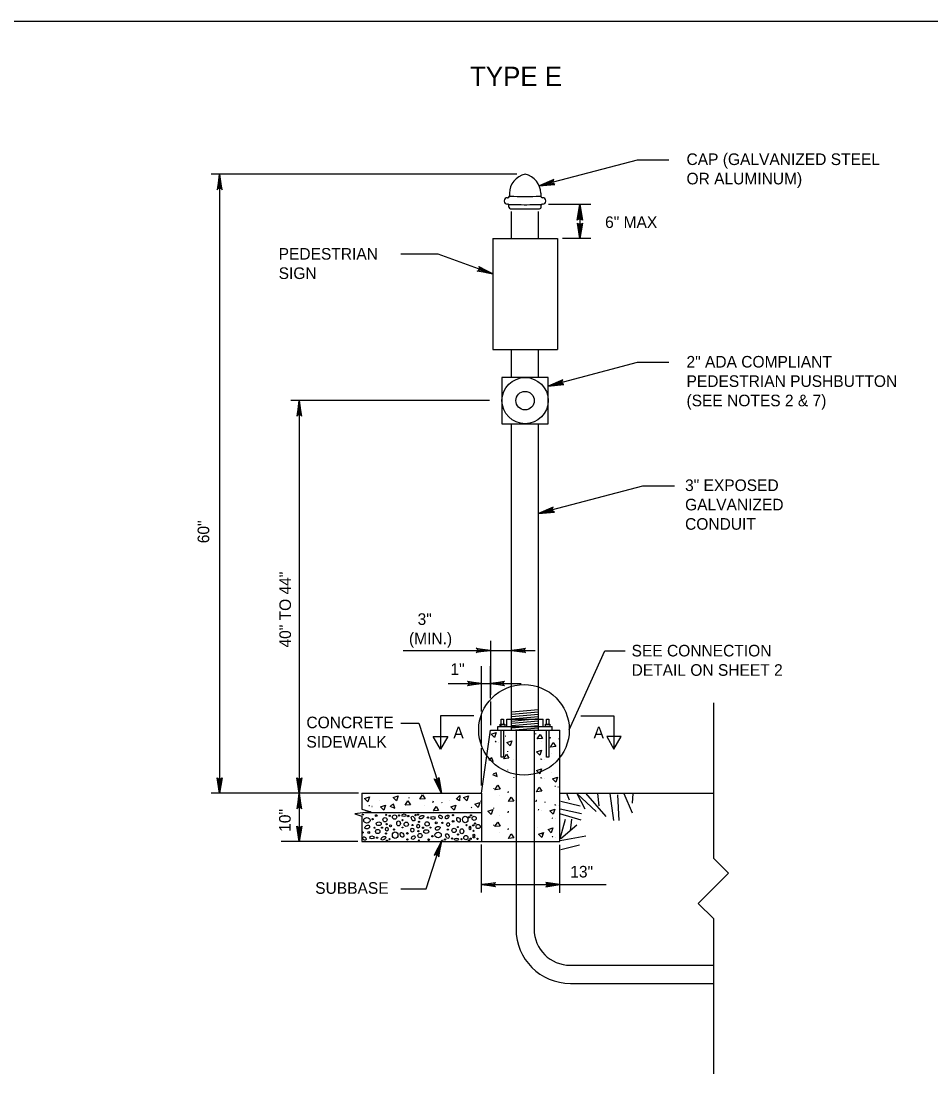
# Model space of a CAD drawing. Extents: x 36 to 940, y -1166 to 1210.
# Drawn here: x 329.9 to 564.8, y -264.7 to 7.2 of the extents above; entities that cross this region are included whole.
import ezdxf

# ---------------------------------------------------------------- set-up
doc = ezdxf.new("R2010")
doc.units = 0
for name, color, linetype in [('1', 7, 'Continuous'), ('2', 7, 'Continuous'), ('Default', 7, 'Continuous'), ('DIM TXT', 7, 'Continuous')]:
    doc.layers.add(name, color=color, linetype=linetype)

msp = doc.modelspace()

# ---------------------------------------------------------------- linework, layer by layer
at = {"layer": '1'}
for p, q in [((75.86, 7.17), (861.86, 7.17)), ((488.95, -28.72), (463.7, -35.39)), ((497.16, -28.72), (488.95, -28.72)), ((476.98, -40.17), (466.11, -40.17)), ((474.19, -40.17), (474.19, -49)), ((476.98, -49), (469.71, -49)), ((427.98, -52.97), (437.5, -52.97)), ((437.5, -52.97), (451.69, -58.09)), ((488.95, -81.02), (466.01, -87.09)), ((497.16, -81.02), (488.95, -81.02)), ((490.37, -112.9), (463.55, -119.99)), ((498.58, -112.9), (490.37, -112.9)), ((451.08, -152.85), (451.08, -166.8)), ((428.61, -155.34), (462.68, -155.34)), ((471.46, -175.86), (480.61, -155.5)), ((480.61, -155.5), (485.84, -155.5)), ((448.81, -171.16), (448.81, -159.38)), ((451.08, -167.64), (451.08, -159.38)), ((440.17, -163.88), (458.99, -163.88)), ((451.08, -168.57), (451.08, -174.69)), ((456.53, -171.24), (463.55, -170.62)), ((456.53, -171.82), (463.55, -171.21)), ((448.81, -179.38), (448.81, -172.19)), ((455.37, -175), (455.37, -173.13)), ((455.37, -173.13), (464.72, -173.13)), ((455.37, -175), (455.37, -173.13)), ((456.53, -172.41), (463.55, -171.8)), ((456.53, -173), (463.55, -172.38)), ((456.53, -173.58), (463.55, -172.97)), ((456.53, -174.17), (463.55, -173.56)), ((464.72, -175), (464.72, -173.13)), ((464.72, -175), (464.72, -173.13)), ((427.98, -174.15), (432.64, -174.15)), ((432.64, -174.15), (438.44, -192.17)), ((453.03, -175.93), (453.03, -175)), ((453.03, -175), (467.06, -175)), ((453.03, -175.93), (453.03, -175)), ((453.03, -175.93), (467.06, -175.93)), ((456.53, -174.76), (463.55, -174.14)), ((456.53, -175.34), (463.55, -174.73)), ((456.53, -175.93), (463.55, -175.32)), ((467.06, -175.93), (467.06, -175)), ((467.06, -175.93), (467.06, -175)), ((448.81, -190.24), (448.81, -180.59)), ((401.72, -192.24), (401.72, -204.72)), ((417.87, -192.24), (448.81, -192.24)), ((469.01, -192.24), (508.66, -192.24)), ((470.73, -192.24), (471.41, -193.92)), ((473.37, -192.31), (475.51, -196.25)), ((473.37, -192.31), (478.37, -196.96)), ((475.61, -192.24), (480.87, -198.21)), ((478.73, -192.31), (479.08, -195.52)), ((481.95, -192.31), (482.84, -199.28)), ((483.91, -192.67), (484.27, -199.28)), ((485.53, -192.31), (487.67, -197.32)), ((487.84, -192.31), (487.67, -194.82)), ((469.25, -194.27), (474.26, -195.52)), ((418.57, -197.23), (448.81, -197.23)), ((468.9, -197.49), (474.44, -199.1)), ((469.08, -196.25), (474.62, -197.49)), ((469.08, -203.92), (470.5, -198.92)), ((469.25, -203.92), (473.37, -200.36)), ((471.75, -201.96), (472.12, -198.92)), ((469.08, -204.46), (475.69, -203.21)), ((416.86, -204.72), (397.04, -204.72)), ((417.87, -204.72), (448.81, -204.72)), ((434.49, -216.9), (438.44, -204.63)), ((448.81, -217.88), (448.81, -205.48)), ((469.01, -217.99), (469.01, -205.56)), ((469.25, -206.79), (474.08, -205.54)), ((427.98, -216.9), (434.49, -216.9)), ((448.81, -215.84), (481.02, -215.84))]:
    msp.add_line(p, q, dxfattribs=at)
for points in [[(381.64, -36.18), (381.37, -36.03), (381.16, -32.35), (381.64, -36.18), (381.81, -36.37), (381.16, -32.35), (380.98, -36.03), (380.71, -36.16), (381.16, -32.35), (380.52, -36.37), (380.71, -36.16)], [(467.28, -33.98), (467.21, -34.28), (463.7, -35.39), (467.28, -33.98), (467.43, -33.77), (463.7, -35.39), (467.3, -34.66), (467.5, -34.89), (463.7, -35.39), (467.75, -35.02), (467.5, -34.89)], [(473.7, -44.05), (473.98, -43.91), (474.19, -40.17), (473.7, -44.05), (473.53, -44.25), (474.19, -40.17), (474.37, -43.9), (474.65, -44.04), (474.19, -40.17), (474.84, -44.25), (474.65, -44.04)], [(474.67, -45.18), (474.39, -45.32), (474.19, -49), (474.67, -45.18), (474.83, -44.98), (474.19, -49), (474, -45.32), (473.73, -45.19), (474.19, -49), (473.55, -44.98), (473.73, -45.19)], [(448.21, -56.41), (448.26, -56.72), (451.69, -58.09), (448.21, -56.41), (448.08, -56.19), (451.69, -58.09), (448.14, -57.09), (447.93, -57.31), (451.69, -58.09), (447.67, -57.41), (447.93, -57.31)], [(469.6, -85.67), (469.53, -85.98), (466.01, -87.09), (469.6, -85.67), (469.75, -85.46), (466.01, -87.09), (469.62, -86.35), (469.82, -86.58), (466.01, -87.09), (470.06, -86.71), (469.82, -86.58)], [(402.2, -94.68), (401.92, -94.53), (401.72, -90.85), (402.2, -94.68), (402.37, -94.87), (401.72, -90.85), (401.54, -94.53), (401.27, -94.66), (401.72, -90.85), (401.08, -94.87), (401.27, -94.66)], [(467.14, -118.57), (467.07, -118.88), (463.55, -119.99), (467.14, -118.57), (467.28, -118.36), (463.55, -119.99), (467.16, -119.25), (467.36, -119.48), (463.55, -119.99), (467.6, -119.61), (467.36, -119.48)], [(447.63, -154.91), (447.75, -155.16), (451.08, -155.34), (447.63, -154.91), (447.45, -154.76), (451.08, -155.34), (447.76, -155.51), (447.63, -155.75), (451.08, -155.34), (447.45, -155.92), (447.63, -155.75)], [(459.99, -155.78), (459.86, -155.53), (456.53, -155.34), (459.99, -155.78), (460.16, -155.93), (456.53, -155.34), (459.86, -155.18), (459.98, -154.93), (456.53, -155.34), (460.16, -154.77), (459.98, -154.93)], [(445.36, -163.45), (445.49, -163.7), (448.81, -163.88), (445.36, -163.45), (445.18, -163.3), (448.81, -163.88), (445.49, -164.05), (445.37, -164.29), (448.81, -163.88), (445.18, -164.46), (445.37, -164.29)], [(454.53, -164.32), (454.4, -164.07), (451.08, -163.88), (454.53, -164.32), (454.71, -164.47), (451.08, -163.88), (454.4, -163.72), (454.52, -163.47), (451.08, -163.88), (454.71, -163.31), (454.52, -163.47)], [(508.66, -168.86), (508.66, -208.99), (512.55, -212.89), (504.76, -220.68), (508.66, -224.58), (508.66, -264.72)], [(453.9, -174.41), (453.9, -173.13), (454.49, -173.13), (454.49, -174.41)], [(465.59, -174.41), (465.59, -173.13), (466.18, -173.13), (466.18, -174.41)], [(451.25, -177.01), (452.55, -176.58), (452.12, -177.88), (451.25, -177.01)], [(451.25, -177.01), (452.55, -176.58), (452.12, -177.88), (451.25, -177.01)], [(453.9, -175), (453.9, -174.41)], [(454.49, -175.93), (454.49, -182.95), (453.9, -182.95), (453.9, -175.93)], [(466.18, -175.93), (466.18, -182.95), (465.59, -182.95), (465.59, -175.93)], [(455.36, -179.16), (456.65, -178.73), (456.22, -180.03), (455.36, -179.16)], [(464.54, -178.11), (463.18, -178.22), (463.9, -177.07), (464.54, -178.11)], [(467.94, -180.18), (466.58, -180.3), (467.31, -179.14), (467.94, -180.18)], [(467.94, -180.18), (466.58, -180.3), (467.31, -179.14), (467.94, -180.18)], [(463.01, -181.57), (464.3, -181.14), (463.87, -182.43), (463.01, -181.57)], [(463.01, -181.57), (464.3, -181.14), (463.87, -182.43), (463.01, -181.57)], [(455.89, -183.21), (454.53, -183.32), (455.25, -182.17), (455.89, -183.21)], [(463.01, -186.37), (464.3, -185.94), (463.87, -187.23), (463.01, -186.37)], [(463.01, -186.37), (464.3, -185.94), (463.87, -187.23), (463.01, -186.37)], [(381.64, -188.41), (381.37, -188.56), (381.16, -192.24), (381.64, -188.41), (381.81, -188.22), (381.16, -192.24), (380.98, -188.56), (380.71, -188.42), (381.16, -192.24), (380.52, -188.22), (380.71, -188.42)], [(402.2, -188.41), (401.92, -188.56), (401.72, -192.24), (402.2, -188.41), (402.37, -188.22), (401.72, -192.24), (401.54, -188.56), (401.27, -188.42), (401.72, -192.24), (401.08, -188.22), (401.27, -188.42)], [(437.71, -188.38), (437.49, -188.6), (438.44, -192.17), (437.71, -188.38), (437.8, -188.14), (438.44, -192.17), (437.12, -188.73), (436.82, -188.68), (438.44, -192.17), (436.58, -188.54), (436.82, -188.68)], [(453.62, -191.2), (452.26, -191.31), (452.99, -190.15), (453.62, -191.2)], [(467.11, -188.52), (468.41, -188.09), (467.98, -189.38), (467.11, -188.52)], [(402.2, -196.06), (401.92, -195.92), (401.72, -192.24), (402.2, -196.06), (402.37, -196.26), (401.72, -192.24), (401.54, -195.92), (401.27, -196.05), (401.72, -192.24), (401.08, -196.26), (401.27, -196.05)], [(417.87, -192.24), (417.87, -196.33), (420.2, -197.03), (416.08, -197.53), (417.87, -198.12), (417.87, -204.72)], [(426, -193.3), (427.3, -192.87), (426.87, -194.16), (426, -193.3)], [(434.23, -193.64), (432.87, -193.76), (433.6, -192.6), (434.23, -193.64)], [(444.16, -193.3), (445.46, -192.87), (445.02, -194.16), (444.16, -193.3)], [(464.35, -191.73), (462.99, -191.84), (463.71, -190.69), (464.35, -191.73)], [(464.35, -191.73), (462.99, -191.84), (463.71, -190.69), (464.35, -191.73)], [(418.58, -193.56), (419.88, -193.13), (419.45, -194.43), (418.58, -193.56)], [(418.58, -193.56), (419.88, -193.13), (419.45, -194.43), (418.58, -193.56)], [(422.69, -195.71), (423.99, -195.28), (423.55, -196.58), (422.69, -195.71)], [(430.44, -195.21), (429.08, -195.32), (429.81, -194.16), (430.44, -195.21)], [(437.72, -196.7), (436.36, -196.81), (437.08, -195.66), (437.72, -196.7)], [(437.72, -196.7), (436.36, -196.81), (437.08, -195.66), (437.72, -196.7)], [(440.85, -195.71), (442.14, -195.28), (441.71, -196.58), (440.85, -195.71)], [(447.03, -195.08), (448.33, -194.65), (447.9, -195.95), (447.03, -195.08)], [(457.11, -194.25), (455.75, -194.37), (456.47, -193.21), (457.11, -194.25)], [(457.11, -194.25), (455.75, -194.37), (456.47, -193.21), (457.11, -194.25)], [(450.4, -196.86), (451.7, -196.42), (451.27, -197.72), (450.4, -196.86)], [(466.44, -196.75), (467.73, -196.32), (467.3, -197.62), (466.44, -196.75)], [(402.2, -200.89), (401.92, -201.03), (401.72, -204.72), (402.2, -200.89), (402.37, -200.7), (401.72, -204.72), (401.54, -201.04), (401.27, -200.9), (401.72, -204.72), (401.08, -200.7), (401.27, -200.9)], [(453.62, -200.72), (452.26, -200.83), (452.99, -199.68), (453.62, -200.72)], [(465.96, -201.59), (467.25, -201.16), (466.82, -202.46), (465.96, -201.59)], [(465.96, -201.59), (467.25, -201.16), (466.82, -202.46), (465.96, -201.59)], [(457.11, -203.78), (455.75, -203.89), (456.47, -202.74), (457.11, -203.78)], [(457.11, -203.78), (455.75, -203.89), (456.47, -202.74), (457.11, -203.78)], [(463.5, -202.76), (464.79, -202.33), (464.36, -203.62), (463.5, -202.76)], [(437.71, -208.42), (437.49, -208.19), (438.44, -204.63), (437.71, -208.42), (437.8, -208.65), (438.44, -204.63), (437.12, -208.07), (436.82, -208.11), (438.44, -204.63), (436.58, -208.25), (436.82, -208.11)], [(452.27, -216.27), (452.14, -216.02), (448.81, -215.84), (452.27, -216.27), (452.44, -216.42), (448.81, -215.84), (452.13, -215.67), (452.26, -215.43), (448.81, -215.84), (452.44, -215.26), (452.26, -215.43)], [(465.58, -216.27), (465.71, -216.02), (469.03, -215.84), (465.58, -216.27), (465.4, -216.42), (469.03, -215.84), (465.71, -215.67), (465.59, -215.43), (469.03, -215.84), (465.4, -215.26), (465.59, -215.43)]]:
    msp.add_lwpolyline(points, dxfattribs=at)
for points in [[(453.61, -175), (453.61, -174.41), (454.78, -174.41), (454.78, -175)], [(465.3, -175), (465.3, -174.41), (466.47, -174.41), (466.47, -175)]]:
    msp.add_lwpolyline(points, close=True, dxfattribs=at)
for centre, radius in [((459.77, -175.86), 11.69), ((453.19, -179.07), 0.00223), ((455.03, -177.46), 0.00223), ((455.03, -177.46), 0.00223), ((464.38, -178.85), 0.00223), ((464.38, -178.85), 0.00223), ((466.55, -177.72), 0.00223), ((466.79, -182.02), 0.00223), ((466.79, -182.02), 0.00223), ((457.15, -183.41), 0.00223), ((457.15, -183.41), 0.00223), ((464.94, -183.63), 0.00223), ((466.79, -186.82), 0.00223), ((466.79, -186.82), 0.00223), ((457.15, -188.21), 0.00223), ((457.15, -188.21), 0.00223), ((464.94, -188.43), 0.00223), ((453.54, -192.92), 0.00223), ((453.54, -192.92), 0.00223), ((455.71, -191.79), 0.00223), ((463.17, -191.53), 0.00223), ((463.17, -191.53), 0.00223), ((468.57, -190.62), 0.00223), ((420.52, -195.62), 0.00223), ((422.36, -194.01), 0.00223), ((422.36, -194.01), 0.00223), ((434.15, -195.37), 0.00223), ((434.15, -195.37), 0.00223), ((436.32, -194.24), 0.00223), ((440.52, -194.01), 0.00223), ((440.52, -194.01), 0.00223), ((462.95, -194.07), 0.00223), ((468.57, -195.42), 0.00223), ((470.41, -193.81), 0.00223), ((470.41, -193.81), 0.00223), ((418.15, -197.76), 0.155), ((421.63, -198.01), 0.233), ((424.19, -197.82), 0.155), ((425.09, -198.08), 0.155), ((426.35, -198.39), 0.544), ((427.47, -197.98), 0.155), ((429.9, -198.13), 0.155), ((431.75, -197.87), 0.155), ((432.39, -197.77), 0.155), ((434.96, -198.52), 0.155), ((439.97, -198.26), 0.00223), ((441.45, -197.89), 0.155), ((445.64, -198.41), 0.155), ((446.07, -197.95), 0.155), ((446.9, -198.72), 0.544), ((453.54, -198.05), 0.00223), ((453.54, -198.05), 0.00223), ((455.71, -196.92), 0.00223), ((463.17, -196.66), 0.00223), ((463.17, -196.66), 0.00223), ((464.27, -196.66), 0.00223), ((420.68, -198.91), 0.155), ((421.19, -201.13), 0.123), ((423.09, -201.11), 0.155), ((423.88, -199.08), 0.544), ((424.29, -200.2), 0.155), ((425.28, -200.63), 0.233), ((428.38, -199.18), 0.155), ((428.4, -201.08), 0.123), ((429.38, -200.25), 0.557), ((430.99, -200.44), 0.155), ((432.65, -199.61), 0.155), ((433.7, -201.14), 0.155), ((434.76, -200.14), 0.557), ((435.6, -201.12), 0.123), ((437.11, -199.86), 0.233), ((438.7, -199.87), 0.155), ((441.45, -199.48), 0.233), ((442.71, -200.98), 0.123), ((444.92, -200.48), 0.155), ((445.82, -200.96), 0.233), ((446.66, -200.52), 0.155), ((447.09, -200.06), 0.155), ((447.92, -200.83), 0.544), ((463.17, -201.06), 0.00223), ((463.17, -201.06), 0.00223), ((467.9, -198.85), 0.00223), ((418.09, -202.38), 0.155), ((419.68, -202.38), 0.233), ((422.02, -202.11), 0.557), ((421.83, -203.72), 0.155), ((424.14, -202.63), 0.155), ((426.18, -201.59), 0.155), ((429.65, -202.59), 0.233), ((432.5, -202.04), 0.155), ((432.91, -203.17), 0.544), ((436.11, -203.34), 0.155), ((440.11, -201.63), 0.155), ((441.2, -203.94), 0.155), ((441.72, -201.82), 0.557), ((442.72, -202.88), 0.155), ((444.75, -203.68), 0.544), ((445.82, -201.43), 0.233), ((446.01, -203.98), 0.155), ((446.73, -201.92), 0.155), ((446.84, -203.07), 0.233), ((446.84, -203.54), 0.233), ((447.74, -204.03), 0.155), ((453.54, -202.45), 0.00223), ((453.54, -202.45), 0.00223), ((455.71, -201.32), 0.00223), ((467.9, -203.65), 0.00223), ((469.74, -202.04), 0.00223), ((469.74, -202.04), 0.00223), ((424.39, -204.48), 0.155), ((425.03, -204.11), 0.155), ((429.65, -204.18), 0.155), ((432.6, -204.42), 0.155), ((435.15, -204.24), 0.233), ((438.63, -204.49), 0.155), ((439.36, -204.19), 0.155), ((443.63, -204.09), 0.155), ((445.58, -204.44), 0.155)]:
    msp.add_circle(centre, radius, dxfattribs=at)
for centre, major_axis, ratio in [((428.79, -197.92), (-0.531, 0), 0.634146), ((431.12, -198.78), (-0.311, 0.57), 0.595541), ((433.3, -198.4), (-0.57, -0.311), 0.595541), ((436.28, -198.6), (-0.541, 0), 0.718164), ((438.21, -198.33), (-0.362, 0.401), 0.692837), ((439.92, -198.37), (-0.401, -0.362), 0.692837), ((442.85, -199.09), (0.259, -0.595), 0.671701), ((444.59, -199.02), (0, -0.847), 0.840503), ((419.22, -199.24), (0.847, 0), 0.840503), ((419.3, -200.98), (0.595, 0.259), 0.671701), ((422.25, -200.1), (0.649, 0), 0.737643), ((424.34, -201.52), (0, 0.531), 0.634146), ((427.37, -200.02), (0, 0.649), 0.737643), ((432.44, -200.73), (0, -0.531), 0.634146), ((437.49, -201.26), (-0.595, -0.259), 0.671701), ((440.18, -200.3), (0, -0.541), 0.718164), ((418.57, -203.92), (0.362, -0.401), 0.692837), ((420.51, -203.65), (0.541, 0), 0.718164), ((423.49, -203.85), (0.57, 0.311), 0.595541), ((426.51, -203.05), (0, 0.847), 0.840503), ((428.25, -202.97), (-0.259, 0.595), 0.671701), ((430.92, -201.76), (0, 0.541), 0.718164), ((431.18, -203.69), (0.401, 0.362), 0.692837), ((434.54, -202.14), (-0.649, 0), 0.737643), ((437.57, -203.01), (-0.847, 0), 0.840503), ((439.98, -203.29), (0.311, -0.57), 0.595541), ((442.31, -204.14), (0.531, 0), 0.634146), ((443.73, -202.05), (0, -0.649), 0.737643)]:
    msp.add_ellipse(centre, major_axis=major_axis, ratio=ratio, dxfattribs=at)
at = {"layer": 'Default'}
for p, q in [((457.93, -32.35), (379.01, -32.35)), ((381.16, -32.35), (381.16, -192.24)), ((455.98, -37.31), (455.98, -38.05)), ((464.1, -37.31), (464.1, -38.05)), ((455.51, -38.44), (455.57, -38.44)), ((455.67, -40.13), (455.51, -40.13)), ((455.87, -40.88), (455.87, -40.33)), ((464.21, -40.88), (464.21, -40.33)), ((464.58, -40.13), (464.42, -40.13)), ((464.52, -38.44), (464.58, -38.44)), ((465.41, -39.34), (465.41, -39.24)), ((456.29, -41.28), (463.79, -41.28)), ((456.53, -49), (456.53, -42.02)), ((463.55, -49), (463.55, -42.02)), ((451.69, -49), (468.4, -49)), ((451.69, -49), (451.69, -77.65)), ((468.4, -49), (468.4, -77.65)), ((451.69, -77.65), (468.4, -77.65)), ((456.53, -84.88), (456.53, -77.65)), ((463.55, -84.88), (463.55, -77.65)), ((450.85, -90.85), (399.57, -90.85)), ((401.72, -90.85), (401.72, -192.24)), ((454.07, -96.82), (466.01, -96.82)), ((456.53, -175.93), (456.53, -96.82)), ((463.55, -175.93), (463.55, -96.82)), ((448.81, -192.24), (451.08, -175.93)), ((451.08, -175.93), (469.01, -175.93)), ((457.7, -175.93), (457.7, -227.31)), ((462.38, -175.93), (462.38, -227.31)), ((469.01, -204.72), (469.01, -175.93)), ((452.36, -178.88), (452.44, -178.81)), ((452.54, -178.95), (452.36, -178.92)), ((452.44, -178.81), (452.54, -178.95)), ((462.79, -176.95), (462.82, -176.81)), ((466.49, -178.06), (466.6, -177.71)), ((468.85, -178.28), (468.82, -178.06)), ((455.56, -181.51), (455.6, -181.36)), ((464.12, -183.44), (464.19, -183.37)), ((464.3, -183.51), (464.12, -183.47)), ((464.19, -183.37), (464.3, -183.51)), ((455.56, -186.31), (455.6, -186.16)), ((464.12, -188.24), (464.19, -188.17)), ((464.3, -188.31), (464.12, -188.28)), ((464.19, -188.17), (464.3, -188.31)), ((417.01, -192.24), (379.01, -192.24)), ((448.81, -192.24), (448.81, -204.72)), ((451.95, -191.02), (451.98, -190.88)), ((455.65, -192.13), (455.76, -191.77)), ((467.92, -190.5), (467.74, -190.46)), ((419.7, -195.43), (419.77, -195.36)), ((419.87, -195.51), (419.7, -195.47)), ((419.77, -195.36), (419.87, -195.51)), ((430.12, -193.5), (430.15, -193.36)), ((436.26, -194.58), (436.37, -194.22)), ((438.63, -194.79), (438.59, -194.58)), ((448.58, -194.37), (448.61, -194.23)), ((462.89, -194.41), (463, -194.05)), ((465.25, -194.63), (465.22, -194.41)), ((467.74, -195.23), (467.81, -195.16)), ((467.92, -195.3), (467.74, -195.27)), ((467.81, -195.16), (467.92, -195.3)), ((446.3, -195.79), (446.15, -196.01)), ((451.95, -196.14), (451.98, -196)), ((455.65, -197.26), (455.76, -196.9)), ((463.44, -196.47), (463.52, -196.4)), ((463.62, -196.54), (463.44, -196.51)), ((463.52, -196.4), (463.62, -196.54)), ((451.95, -200.55), (451.98, -200.4)), ((467.25, -198.73), (467.07, -198.7)), ((455.65, -201.66), (455.76, -201.3)), ((464.58, -202.86), (464.54, -202.64)), ((467.07, -203.46), (467.14, -203.39)), ((467.25, -203.53), (467.07, -203.5)), ((467.14, -203.39), (467.25, -203.53)), ((448.81, -204.72), (468.98, -204.72)), ((471.73, -236.66), (508.66, -236.66)), ((471.73, -241.34), (508.66, -241.34))]:
    msp.add_line(p, q, dxfattribs=at)
for points in [[(466.01, -96.82), (466.01, -84.88), (454.07, -84.88), (454.07, -96.82), (454.07, -96.82)], [(450.61, -183.55), (451.83, -184.05), (451.5, -183.09), (450.75, -183.48)], [(451.65, -187.39), (452.87, -187.89), (452.55, -186.92), (451.8, -187.32)], [(442.28, -193.72), (443.17, -192.82), (443.1, -194.22), (442.42, -193.72)], [(425.16, -195.55), (426.38, -196.05), (426.06, -195.08), (425.3, -195.47)]]:
    msp.add_lwpolyline(points, dxfattribs=at)
for radius in [5.97, 2.39]:
    msp.add_circle((460.04, -90.85), radius, dxfattribs=at)
for radius in [14.03, 9.35]:
    msp.add_arc((471.73, -227.31), radius, 180, 270, dxfattribs=at)
for centre, major_axis, ratio, start_param, end_param in [((461.41, -37.35), (5.43, 0), 0.952381, 1.825494, 3.132766), ((458.67, -37.35), (5.43, 0), 0.952381, 0.008827, 1.316099), ((455.57, -38.05), (0.417, 0), 0.952381, 4.712389, 6.283185), ((460.04, -38.05), (-4.06, 0), 0.012269, 0, 3.141593), ((464.52, -38.05), (0.417, 0), 0.952381, 3.141593, 4.712389), ((455.51, -39.24), (0.833, 0), 0.952381, 1.570796, 3.141593), ((455.51, -39.34), (0.833, 0), 0.952381, 3.141593, 4.712389), ((455.67, -40.33), (0.208, 0), 0.952381, 0, 1.570796), ((460.12, -40.13), (-4.46, 0), 0.026054, 0.212556, 2.780907), ((464.42, -40.33), (0.208, 0), 0.952381, 1.570796, 3.141593), ((464.58, -39.24), (0.833, 0), 0.952381, 0, 1.570796), ((464.58, -39.34), (0.833, 0), 0.952381, 4.712389, 6.283185), ((456.29, -40.88), (0.417, 0), 0.952381, 3.141593, 4.712389), ((463.79, -40.88), (0.417, 0), 0.952381, 4.712389, 6.283185)]:
    msp.add_ellipse(centre, major_axis=major_axis, ratio=ratio, start_param=start_param, end_param=end_param, dxfattribs=at)
at = {"layer": 'DIM TXT'}
for points in [[(446.78, -172.26), (438.21, -172.26), (438.21, -180.83)], [(474.42, -172.26), (482.99, -172.26), (482.99, -180.83)]]:
    msp.add_lwpolyline(points, dxfattribs=at)
for points in [[(438.21, -180.83), (436.33, -177.56), (440.1, -177.56)], [(482.99, -180.83), (484.88, -177.56), (481.11, -177.56)]]:
    msp.add_lwpolyline(points, close=True, dxfattribs=at)

# ---------------------------------------------------------------- texts
at = {"layer": '2'}
for s, height, p in [('TYPE E', 5, (445.81, -9.61)), ('CAP (GALVANIZED STEEL', 3, (501.72, -30.01)), ('OR ALUMINUM)', 3, (501.72, -35.01)), ('6" MAX', 3, (480.7, -46.26)), ('PEDESTRIAN', 3, (396.42, -54.44)), ('SIGN', 3, (396.42, -59.44)), ('2" ADA COMPLIANT', 3, (501.72, -82.31)), ('PEDESTRIAN PUSHBUTTON', 3, (501.72, -87.31)), ('(SEE NOTES 2 & 7)', 3, (501.72, -92.31)), ('3" EXPOSED ', 3, (501.35, -114.19)), ('GALVANIZED', 3, (501.35, -119.19)), ('CONDUIT', 3, (501.35, -124.19)), ('  3" ', 3, (430.07, -148.77)), ('(MIN.)', 3, (430.07, -153.77)), ('SEE CONNECTION ', 3, (487.54, -156.91)), ('1"', 3, (440.78, -161.68)), ('DETAIL ON SHEET 2', 3, (487.54, -161.91)), ('CONCRETE', 3, (403.59, -175.45)), ('SIDEWALK', 3, (403.59, -180.45)), ('13"', 3, (471.71, -213.99)), ('SUBBASE', 3, (405.86, -218.2))]:
    msp.add_text(s, height=height, dxfattribs=at).set_placement(p)
for s, p in [('60"', (378.5, -127.67)), ('40" TO 44"', (399.61, -154.6)), ('10"', (399.53, -202.19))]:
    msp.add_text(s, height=3, rotation=90, dxfattribs=at).set_placement(p)
at = {"layer": 'DIM TXT'}
for p in [(441.52, -178.04), (477.73, -178.04)]:
    msp.add_text('A', height=3, dxfattribs=at).set_placement(p)

doc.saveas('drawing.dxf')
